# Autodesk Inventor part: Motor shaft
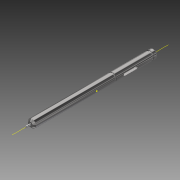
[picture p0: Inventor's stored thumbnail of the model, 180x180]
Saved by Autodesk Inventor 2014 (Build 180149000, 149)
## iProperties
Created: 2008-06
Part Number: Motor shaft
Document SubType Name: Modeling
Designer: tangg
Density: 7.84 g/cm^3
Mass: 17.005 g
Surface Area: 63.6795 cm^2
Volume: 17.005 cm^3
Material: Steel, High Strength Low Alloy
Appearance: Steel - Polished
Author: tangg
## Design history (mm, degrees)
sketch "Sketch1"
  geometry: C1 r 5 at (0, 0); 1 further point
  constraints: 1 centre point, 1 coincident
  dimensions: "d0" = 10 diameter of C1
extrude "Extrusion1" new body sketch "Sketch1" stored distance "d1" = 152.4; taper "d2" = 0 deg
workplane "Work Plane4"
workplane "Work Plane5"
workplane "Work Plane6"
sketch "Sketch6"
  geometry: 1 further point
sketch "Sketch7"
  geometry: L1 (0, 106.68)-(0, -106.68) reference; L2 (-1.5, -49.215)-(-1.527, -34.925); L3 (1.473, -34.919)-(1.5, -49.21); L4 (-1.5, -49.215)-(1.5, -49.21); L5 (-1.527, -34.925)-(1.473, -34.919); A1 r 1.5 centre (0, -49.212) between (-1.5, -49.215) and (1.5, -49.21); A2 r 1.5 centre (-0.027, -34.922) between (1.473, -34.919) and (-1.527, -34.925); 2 further points
  constraints: 8 end point, 5 point on circle, 3 tangent, 2 centre point, 2 midpoint, 1 coincident, 1 point on line
  dimensions: "d28" = 3 distance between parallel lines of L2 L3
extrude "Extrusion2" cut sketch "Sketch7" distance "d29" = 3; taper "d30" = 0 deg
chamfer "Chamfer2" distance "d42" = 2; stored, may be unused: second distance "d43" = 2, angle "d44" = 45 deg
chamfer "Chamfer3" distance "d45" = 2; stored, may be unused: second distance "d46" = 2, angle "d47" = 45 deg
sketch "Sketch8"
  geometry: C1 r 1 at (0, 0); 1 further point
  constraints: 1 centre point, 1 coincident
  dimensions: "d48" = 2 diameter of C1
extrude "Extrusion3" join sketch "Sketch8" distance "d49" = 6; taper "d50" = 0 deg
fillet "Fillet1" dims "d51" = 0.2
sketch "Sketch9"
  geometry: L1 (-5, -74.2)-(5, -74.2) reference; L2 (-1.5, -49.215)-(-1.527, -34.925) reference; L3 (1.473, -34.919)-(1.5, -49.21) reference; L4 (5, 74.2)-(-5, 74.2) reference; L5 (-5, -74.2)-(-5, 74.2) reference; L6 (0, -103.88)-(0, 103.88) reference; C1 r 1 at (-5, -69.85); C2 r 0.75 at (-5, -23.812); 3 further points
  constraints: 2 centre point, 2 point on line, 4 other
  dimensions: "d53" = 2 diameter of C1; "d54" = 1.5 diameter of C2
revolve "Revolution4" sketch "Sketch9" stored, may be unused: angle "d52" = 90 deg
body "Solid1"
node "Projected Loop3"
other parameters: "d27" = -2
